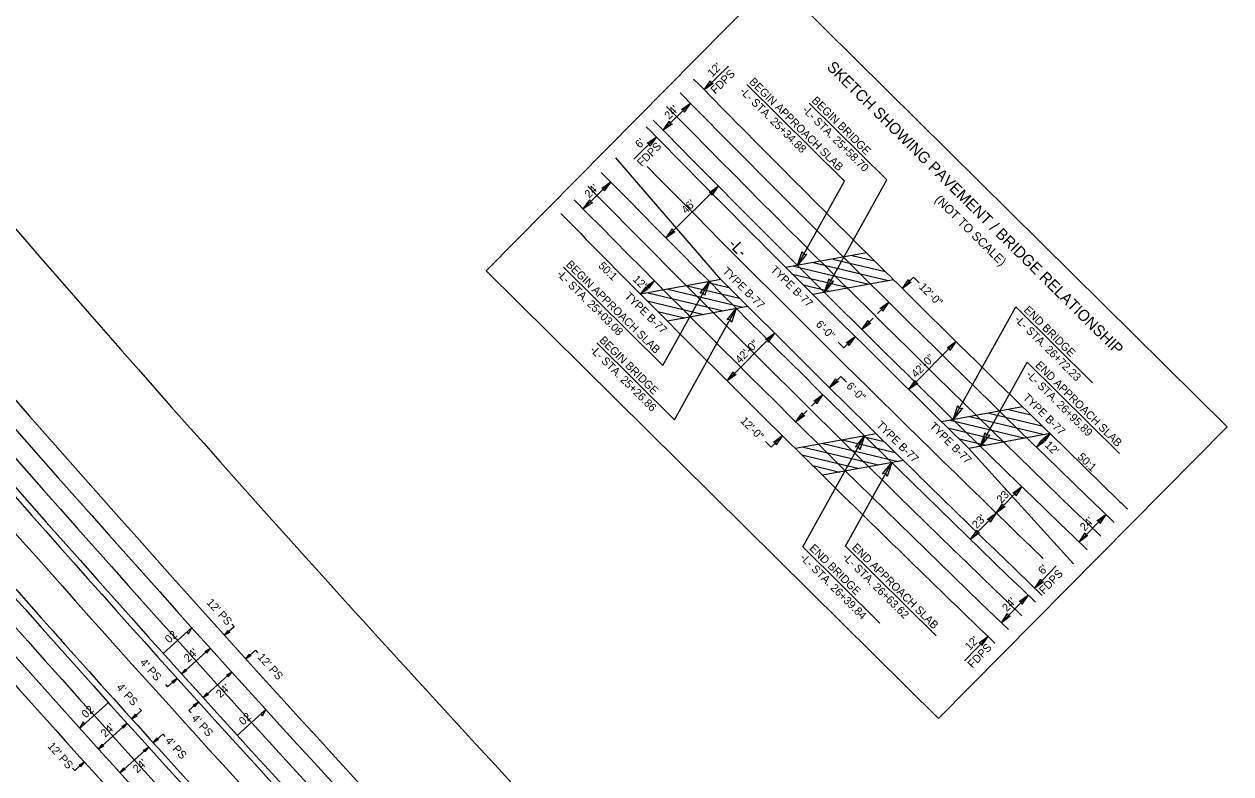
# Model space of a CAD drawing. Extents: x 1602193 to 1605074, y 908180 to 910630.
# Drawn here: x 1602900 to 1603654, y 909541 to 910009 of the extents above; entities that cross this region are included whole.
import ezdxf

# ---------------------------------------------------------------- set-up
doc = ezdxf.new("R2010")
doc.units = 0
for name, color, linetype in [('Prop Approach Slab', 7, 'Continuous'), ('Prop Approach Slab Hatching', 7, 'Continuous'), ('Prop Cable Guiderail Double Face', 7, 'Continuous'), ('Prop Dimension', 7, 'Continuous'), ('Prop Dimension Text', 7, 'Continuous'), ('Prop DSN Text', 7, 'Continuous'), ('Prop EOT', 7, 'Continuous'), ('Prop Fence Woven Wire', 7, 'Continuous'), ('Prop Horizontal Alignment', 7, 'Continuous'), ('Prop Horizontal Alignment Station Label', 7, 'Continuous'), ('Prop Lane Lines', 7, 'Continuous'), ('Prop Paved Shoulder', 7, 'Continuous'), ('Prop Roadway Bridge', 7, 'Continuous'), ('Prop Structure Anchor Unit CELL', 7, 'Continuous'), ('Prop Superelevation  Arrow CELL', 7, 'Continuous'), ('Prop Superelevation Label', 7, 'Continuous'), ('Prop Terminator CELL', 7, 'Continuous')]:
    doc.layers.add(name, color=color, linetype=linetype)

msp = doc.modelspace()

# ---------------------------------------------------------------- linework, layer by layer
at = {"layer": 'Prop Approach Slab'}
for p, q in [((1603426.15, 909865.89), (1603375.89, 909856.69)), ((1603335.26, 909849.24), (1603285.14, 909840.06)), ((1603540.84, 909753.06), (1603490.19, 909743.78)), ((1603449.24, 909736.28), (1603398.73, 909727.02))]:
    msp.add_line(p, q, dxfattribs=at)
for radius, start, end in [(14299.86, 225.146584, 225.241734), (14341.86, 225.030204, 225.124941), (14375.86, 224.936597, 225.031002), (14417.86, 224.821732, 224.915732), (14299.86, 225.695412, 225.791225), (14341.86, 225.576639, 225.672031), (14375.86, 225.481114, 225.576185), (14417.86, 225.3639, 225.458558)]:
    msp.add_arc((1613511.77, 920003.26), radius, start, end, dxfattribs=at)
at = {"layer": 'Prop Approach Slab Hatching'}
for p, q in [((1603392.97, 909859.82), (1603439.87, 909848.59)), ((1603405.14, 909862.04), (1603437.92, 909854.19)), ((1603417.3, 909864.27), (1603431.1, 909860.97)), ((1603379.93, 909852.66), (1603415.54, 909844.13)), ((1603380.81, 909857.59), (1603427.71, 909846.36)), ((1603302.09, 909843.17), (1603348.99, 909831.94)), ((1603314.25, 909845.4), (1603346.92, 909837.57)), ((1603326.42, 909847.62), (1603340.17, 909844.33)), ((1603386.71, 909845.89), (1603403.38, 909841.9)), ((1603289.2, 909835.97), (1603324.66, 909827.48)), ((1603289.93, 909840.94), (1603336.82, 909829.71)), ((1603295.92, 909829.22), (1603312.49, 909825.25)), ((1603514.87, 909768.13), (1603528.79, 909764.8)), ((1603478.38, 909761.44), (1603525.28, 909750.21)), ((1603490.54, 909763.67), (1603537.45, 909752.44)), ((1603502.7, 909765.9), (1603535.79, 909757.98)), ((1603477.07, 909756.62), (1603513.12, 909747.98)), ((1603399.05, 909746.91), (1603445.96, 909735.68)), ((1603411.21, 909749.14), (1603444.18, 909741.25)), ((1603423.38, 909751.37), (1603437.25, 909748.05)), ((1603484.02, 909749.81), (1603500.96, 909745.76)), ((1603385.74, 909739.82), (1603421.64, 909731.22)), ((1603386.88, 909744.68), (1603433.8, 909733.45)), ((1603392.63, 909733.03), (1603409.47, 909728.99))]:
    msp.add_line(p, q, dxfattribs=at)
at = {"layer": 'Prop Cable Guiderail Double Face'}
msp.add_arc((1613646.31, 919202), 14354.86, 219.580763, 222.768936, dxfattribs=at)
at = {"layer": 'Prop Dimension Text'}
for p, q in [((1603188.56, 909854.76), (1603368.87, 910036.95)), ((1603368.87, 910036.95), (1603651.42, 909757.33)), ((1603324.84, 909967.7), (1603339.91, 909982.54)), ((1603412.36, 909910.74), (1603351.36, 909971.1)), ((1603299.2, 909942.43), (1603316.3, 909959.28)), ((1603438.86, 909911.46), (1603390.43, 909959.39)), ((1603280.88, 909924.39), (1603294.92, 909938.22)), ((1603383.07, 909858), (1603412.36, 909910.74)), ((1603399.87, 909841.26), (1603438.86, 909911.46)), ((1603249.33, 909893.31), (1603266.43, 909910.15)), ((1603300.98, 909875.2), (1603333.64, 909907.59)), ((1603188.56, 909854.76), (1603471.11, 909575.13)), ((1603299.04, 909795.6), (1603236.97, 909857.03)), ((1603455.65, 909850.7), (1603448.61, 909843.6)), ((1603455.65, 909850.7), (1603459.2, 909847.18)), ((1603293.65, 909848.52), (1603285.14, 909840.06)), ((1603299.04, 909795.6), (1603328.1, 909847.93)), ((1603306.26, 909761.72), (1603344.83, 909831.18)), ((1603440.16, 909835.07), (1603433.13, 909827.97)), ((1603480.35, 909761.81), (1603519.42, 909832.16)), ((1603567.31, 909784.75), (1603519.42, 909832.16)), ((1603430.31, 909825.12), (1603423.27, 909818.02)), ((1603339.12, 909786.03), (1603368.75, 909815.79)), ((1603419.05, 909813.76), (1603412.01, 909806.65)), ((1603306.26, 909761.72), (1603257.75, 909809.73)), ((1603412.01, 909806.65), (1603408.46, 909810.17)), ((1603452.63, 909780.6), (1603482.09, 909810.54)), ((1603497.42, 909745.11), (1603526.62, 909797.68)), ((1603584.32, 909740.57), (1603526.62, 909797.68)), ((1603403.18, 909781.63), (1603410.21, 909788.74)), ((1603410.21, 909788.74), (1603413.76, 909785.23)), ((1603391.93, 909770.26), (1603398.96, 909777.37)), ((1603382.08, 909760.3), (1603389.11, 909767.41)), ((1603471.11, 909575.13), (1603651.42, 909757.33)), ((1603532.47, 909744.46), (1603540.84, 909753.06)), ((1603366.61, 909744.66), (1603363.06, 909748.18)), ((1603366.61, 909744.66), (1603373.64, 909751.77)), ((1603386.49, 909682.32), (1603425.01, 909751.67)), ((1603413.04, 909682.78), (1603442.02, 909734.96)), ((1603507.22, 909703.46), (1603523.24, 909719.96)), ((1603491.19, 909686.97), (1603507.22, 909703.46)), ((1603559.03, 909685.32), (1603575.69, 909702.59)), ((1603434.56, 909634.76), (1603386.49, 909682.32)), ((1603469.68, 909626.73), (1603413.04, 909682.78)), ((1603531.26, 909656.53), (1603544.66, 909670.42)), ((1603510.43, 909634.94), (1603527.1, 909652.21)), ((1603031.16, 909632.47), (1603025.22, 909627.11)), ((1603029.82, 909633.96), (1603031.16, 909632.47)), ((1603502.1, 909626.3), (1603487.42, 909611.08)), ((1602998.5, 909602.99), (1603016.31, 909619.07)), ((1603044.46, 909617.73), (1603038.53, 909612.36)), ((1603044.46, 909617.73), (1603045.81, 909616.25)), ((1603011.92, 909588.12), (1603029.71, 909604.23)), ((1602988.25, 909596.43), (1602989.59, 909594.95)), ((1602995.53, 909600.31), (1602989.59, 909594.95)), ((1602973.26, 909580.21), (1602967.32, 909574.84)), ((1602971.92, 909581.69), (1602973.26, 909580.21)), ((1603008.88, 909585.52), (1603002.95, 909580.15)), ((1603002.95, 909580.15), (1603004.29, 909578.67)), ((1602946.54, 909556.08), (1602964.35, 909572.16)), ((1602986.64, 909565.38), (1602980.71, 909560.01)), ((1602986.64, 909565.38), (1602987.98, 909563.9)), ((1602959.96, 909541.21), (1602977.75, 909557.32)), ((1602930.35, 909544.16), (1602931.69, 909542.68)), ((1602937.63, 909548.04), (1602931.69, 909542.68))]:
    msp.add_line(p, q, dxfattribs=at)
at = {"layer": 'Prop DSN Text'}
for points in [[(1603289.89, 909843.37), (1603285.14, 909840.06), (1603288.48, 909844.79), (1603288.68, 909843.59)], [(1603288.9, 909845.21), (1603293.65, 909848.52), (1603290.31, 909843.79), (1603290.1, 909844.99)], [(1603536.15, 909749.67), (1603540.84, 909753.06), (1603537.58, 909748.28), (1603537.35, 909749.48)], [(1603537.17, 909747.85), (1603532.47, 909744.46), (1603535.73, 909749.25), (1603535.96, 909748.05)], [(1603028.49, 909629.17), (1603025.22, 909627.11), (1603027.59, 909630.16), (1603027.69, 909629.35)], [(1603013.04, 909617.02), (1603016.31, 909619.07), (1603013.93, 909616.03), (1603013.83, 909616.84)], [(1603041.8, 909614.42), (1603038.53, 909612.36), (1603040.9, 909615.41), (1603041, 909614.6)], [(1603001.76, 909605.04), (1602998.5, 909602.99), (1603000.87, 909606.03), (1603000.97, 909605.22)], [(1603026.45, 909602.17), (1603029.71, 909604.23), (1603027.34, 909601.18), (1603027.24, 909601.99)], [(1602992.26, 909598.26), (1602995.53, 909600.31), (1602993.15, 909597.27), (1602993.05, 909598.07)], [(1603015.19, 909590.18), (1603011.92, 909588.12), (1603014.29, 909591.16), (1603014.39, 909590.36)], [(1603005.61, 909583.46), (1603008.88, 909585.52), (1603006.51, 909582.47), (1603006.41, 909583.28)], [(1602961.08, 909570.11), (1602964.35, 909572.16), (1602961.98, 909569.12), (1602961.88, 909569.93)], [(1602970.59, 909576.9), (1602967.32, 909574.84), (1602969.69, 909577.89), (1602969.8, 909577.08)], [(1602949.81, 909558.13), (1602946.54, 909556.08), (1602948.91, 909559.13), (1602949.01, 909558.32)], [(1602974.49, 909555.26), (1602977.75, 909557.32), (1602975.38, 909554.27), (1602975.28, 909555.08)], [(1602983.97, 909562.07), (1602980.71, 909560.01), (1602983.08, 909563.06), (1602983.18, 909562.25)], [(1602934.36, 909545.99), (1602937.63, 909548.04), (1602935.25, 909545), (1602935.15, 909545.81)], [(1602963.23, 909543.27), (1602959.96, 909541.21), (1602962.33, 909544.26), (1602962.43, 909543.45)]]:
    msp.add_lwpolyline(points, close=True, dxfattribs=at)
at = {"layer": 'Prop EOT'}
for centre, radius, start, end in [((1613646.31, 919202), 14311.86, 219.480877, 227.661141), ((1613646.31, 919202), 14335.86, 219.480979, 227.66104), ((1613646.31, 919202), 14381.86, 219.480979, 227.66104), ((1613646.31, 919202), 14405.86, 219.479716, 227.662303), ((1613511.77, 920003.26), 14311.86, 224.534023, 226.061438), ((1613511.77, 920003.26), 14335.86, 224.535302, 226.060159), ((1613511.77, 920003.26), 14381.86, 224.53774, 226.05772), ((1613511.77, 920003.26), 14405.86, 224.539006, 226.056454)]:
    msp.add_arc(centre, radius, start, end, dxfattribs=at)
at = {"layer": 'Prop Fence Woven Wire'}
for centre, radius, start, end in [((1613597.21, 919158.4), 14163.95, 218.093461, 222.076817), ((1613600.64, 919155.95), 14423.95, 219.415042, 223.36309), ((1613597.21, 919158.4), 14163.95, 222.076817, 224.234567)]:
    msp.add_arc(centre, radius, start, end, dxfattribs=at)
at = {"layer": 'Prop Horizontal Alignment'}
msp.add_arc((1613511.77, 920003.26), 14358.86, 224.607069, 225.996232, dxfattribs=at)
at = {"layer": 'Prop Lane Lines'}
for centre, radius, start, end in [((1613646.31, 919202), 14323.86, 219.480979, 227.66104), ((1613646.31, 919202), 14393.86, 219.480979, 227.66104), ((1613511.77, 920003.26), 14323.86, 224.534663, 226.060798), ((1613511.77, 920003.26), 14393.86, 224.538374, 226.057086)]:
    msp.add_arc(centre, radius, start, end, dxfattribs=at)
at = {"layer": 'Prop Paved Shoulder'}
for p, q in [((1603335.26, 909849.24), (1603269.59, 909925.26)), ((1603540.84, 909753.06), (1603583.87, 909711.07)), ((1603490.19, 909743.78), (1603555.43, 909671.71))]:
    msp.add_line(p, q, dxfattribs=at)
for centre, radius, start, end in [((1613646.31, 919202), 14299.86, 219.480979, 223.794464), ((1613646.31, 919202), 14339.86, 219.480979, 222.863015), ((1613646.31, 919202), 14377.86, 219.48119, 222.373049), ((1613646.31, 919202), 14417.86, 219.480979, 222.382421), ((1613511.77, 920003.26), 14299.86, 224.533383, 225.146584), ((1613511.77, 920003.26), 14341.86, 224.535621, 225.030203), ((1613511.77, 920003.26), 14417.86, 224.539638, 224.821732), ((1613511.77, 920003.26), 14375.86, 225.576185, 226.058037), ((1613511.77, 920003.26), 14417.86, 225.458558, 226.055822), ((1613511.62, 920003.1), 14299.86, 226.032131, 226.061438)]:
    msp.add_arc(centre, radius, start, end, dxfattribs=at)
at = {"layer": 'Prop Roadway Bridge'}
for p, q in [((1603443, 909849.16), (1603392.69, 909839.94)), ((1603352.01, 909832.49), (1603301.82, 909823.3)), ((1603523.71, 909769.75), (1603473.12, 909760.48)), ((1603432.22, 909752.99), (1603381.76, 909743.75))]:
    msp.add_line(p, q, dxfattribs=at)
for radius, start, end in [(14299.86, 225.241734, 225.695412), (14341.86, 225.124941, 225.576639), (14375.86, 225.031002, 225.481114), (14417.86, 224.915732, 225.3639)]:
    msp.add_arc((1613511.77, 920003.26), radius, start, end, dxfattribs=at)
at = {"layer": 'Prop Superelevation  Arrow CELL'}
for p, q in [((1603004.76, 909631.9), (1602986.91, 909615.85)), ((1602952.71, 909585.09), (1602934.86, 909569.05)), ((1603050.96, 909580.77), (1603033.2, 909564.64))]:
    msp.add_line(p, q, dxfattribs=at)
for points in [[(1603004.76, 909631.9), (1603002.41, 909627.78), (1603002.18, 909629.58)], [(1603050.96, 909580.77), (1603048.64, 909576.64), (1603048.39, 909578.44)], [(1602934.86, 909569.05), (1602937.21, 909573.17), (1602937.44, 909571.36)]]:
    msp.add_lwpolyline(points, close=True, dxfattribs=at)
at = {"layer": 'Prop Terminator CELL'}
for points in [[(1603330.47, 909971.61), (1603324.84, 909967.7), (1603328.84, 909973.32), (1603329.06, 909971.86)], [(1603310.67, 909955.37), (1603316.3, 909959.28), (1603312.3, 909953.66), (1603312.07, 909955.12)], [(1603304.82, 909946.34), (1603299.2, 909942.43), (1603303.19, 909948.05), (1603303.42, 909946.59)], [(1603289.3, 909934.31), (1603294.92, 909938.22), (1603290.93, 909932.6), (1603290.7, 909934.06)], [(1603260.8, 909906.24), (1603266.43, 909910.15), (1603262.44, 909904.53), (1603262.21, 909905.99)], [(1603328.03, 909903.66), (1603333.64, 909907.59), (1603329.67, 909901.96), (1603329.43, 909903.42)], [(1603254.96, 909897.22), (1603249.33, 909893.31), (1603253.32, 909898.93), (1603253.55, 909897.46)], [(1603306.59, 909879.12), (1603300.98, 909875.2), (1603304.96, 909880.83), (1603305.19, 909879.37)], [(1603388.79, 909865.12), (1603383.07, 909858), (1603386.06, 909866.69), (1603386.9, 909864.91)], [(1603388.79, 909865.12), (1603383.07, 909858), (1603386.06, 909866.69), (1603386.9, 909864.91)], [(1603322.37, 909840.82), (1603328.1, 909847.93), (1603325.1, 909839.24), (1603324.26, 909841.03)], [(1603405.59, 909848.37), (1603399.87, 909841.26), (1603402.86, 909849.95), (1603403.7, 909848.16)], [(1603405.59, 909848.37), (1603399.87, 909841.26), (1603402.86, 909849.95), (1603403.7, 909848.16)], [(1603454.18, 909847.57), (1603448.61, 909843.6), (1603452.53, 909849.26), (1603452.78, 909847.81)], [(1603339.11, 909824.06), (1603344.83, 909831.18), (1603341.84, 909822.49), (1603341, 909824.27)], [(1603339.11, 909824.06), (1603344.83, 909831.18), (1603341.84, 909822.49), (1603341, 909824.27)], [(1603434.59, 909831.09), (1603440.16, 909835.07), (1603436.24, 909829.4), (1603435.99, 909830.86)], [(1603428.85, 909822), (1603423.27, 909818.02), (1603427.2, 909823.69), (1603427.44, 909822.23)], [(1603363.17, 909811.83), (1603368.75, 909815.79), (1603364.82, 909810.13), (1603364.57, 909811.59)], [(1603413.48, 909809.78), (1603419.05, 909813.76), (1603415.13, 909808.09), (1603414.88, 909809.55)], [(1603476.53, 909806.54), (1603482.09, 909810.54), (1603478.19, 909804.86), (1603477.94, 909806.32)], [(1603344.71, 909789.99), (1603339.12, 909786.03), (1603343.06, 909791.68), (1603343.3, 909790.22)], [(1603408.75, 909785.61), (1603403.18, 909781.63), (1603407.1, 909787.3), (1603407.34, 909785.84)], [(1603458.2, 909784.6), (1603452.63, 909780.6), (1603456.54, 909786.28), (1603456.79, 909784.83)], [(1603393.38, 909773.38), (1603398.96, 909777.37), (1603395.04, 909771.7), (1603394.79, 909773.15)], [(1603486.07, 909768.92), (1603480.35, 909761.81), (1603483.34, 909770.49), (1603484.18, 909768.71)], [(1603486.07, 909768.92), (1603480.35, 909761.81), (1603483.34, 909770.49), (1603484.18, 909768.71)], [(1603387.65, 909764.28), (1603382.08, 909760.3), (1603386, 909765.97), (1603386.25, 909764.51)], [(1603503.15, 909752.22), (1603497.42, 909745.11), (1603500.42, 909753.8), (1603501.26, 909752.01)], [(1603503.15, 909752.22), (1603497.42, 909745.11), (1603500.42, 909753.8), (1603501.26, 909752.01)], [(1603368.07, 909747.79), (1603373.64, 909751.77), (1603369.72, 909746.1), (1603369.48, 909747.56)], [(1603419.28, 909744.55), (1603425.01, 909751.67), (1603422.01, 909742.98), (1603421.17, 909744.76)], [(1603419.28, 909744.55), (1603425.01, 909751.67), (1603422.01, 909742.98), (1603421.17, 909744.76)], [(1603436.3, 909727.84), (1603442.02, 909734.96), (1603439.03, 909726.27), (1603438.19, 909728.05)], [(1603517.71, 909715.93), (1603523.24, 909719.96), (1603519.38, 909714.26), (1603519.12, 909715.71)], [(1603512.76, 909707.5), (1603507.22, 909703.46), (1603511.09, 909709.17), (1603511.35, 909707.71)], [(1603501.68, 909699.43), (1603507.22, 909703.46), (1603503.35, 909697.76), (1603503.09, 909699.21)], [(1603570.17, 909698.54), (1603575.69, 909702.59), (1603571.85, 909696.87), (1603571.58, 909698.33)], [(1603496.73, 909691), (1603491.19, 909686.97), (1603495.06, 909692.67), (1603495.32, 909691.22)], [(1603564.56, 909689.37), (1603559.03, 909685.32), (1603562.88, 909691.04), (1603563.15, 909689.58)], [(1603536.79, 909660.58), (1603531.26, 909656.53), (1603535.11, 909662.25), (1603535.38, 909660.79)], [(1603521.57, 909648.16), (1603527.1, 909652.21), (1603523.25, 909646.49), (1603522.98, 909647.95)], [(1603515.96, 909638.99), (1603510.43, 909634.94), (1603514.28, 909640.66), (1603514.55, 909639.2)], [(1603498.25, 909620.64), (1603502.1, 909626.3), (1603496.53, 909622.25), (1603497.99, 909622.04)]]:
    msp.add_lwpolyline(points, close=True, dxfattribs=at)

# ---------------------------------------------------------------- texts
at = {"layer": 'Prop Dimension'}
for s, height, p in [('SKETCH SHOWING PAVEMENT / BRIDGE RELATIONSHIP', 7, (1603400.9, 909981.34)), ('(NOT TO SCALE)', 5.5, (1603468.44, 909898.67))]:
    msp.add_text(s, height=height, rotation=315.29764, dxfattribs=at).set_placement(p)
at = {"layer": 'Prop Dimension Text'}
for s, rotation, p in [("12'", 44.57114, (1603329.83, 909975.41)), ('FDPS', 44.57114, (1603331.78, 909964.71)), ('BEGIN APPROACH SLAB', 315.29764, (1603352.53, 909972.29)), ('-L- STA. 25+34.88', 315.29764, (1603346.67, 909966.37)), ('BEGIN BRIDGE', 315.29764, (1603391.6, 909960.57)), ("24'", 44.57114, (1603302.88, 909948.87)), ('-L- STA. 25+58.70', 315.29764, (1603385.74, 909954.65)), ("6'", 44.57114, (1603284.63, 909930.89)), ('FDPS', 44.57114, (1603285.79, 909919.4)), ("24'", 44.57114, (1603253.01, 909899.74)), ("46'", 44.76694, (1603313.5, 909889.96)), ('BEGIN APPROACH SLAB', 315.29764, (1603238.14, 909858.21)), ('50:1', 315.70105, (1603258.32, 909857.34)), ('-L- STA. 25+03.08', 315.29764, (1603232.28, 909852.29)), ("12'", 315.29764, (1603279.82, 909848.94)), ('12\'-0"', 315.29764, (1603458.63, 909844.23)), ('END BRIDGE', 315.29764, (1603524.14, 909829.82)), ('6\'-0"', 315.29764, (1603394.16, 909820.81)), ('-L- STA. 26+72.23', 315.29764, (1603518.28, 909823.9)), ('BEGIN BRIDGE', 315.29764, (1603258.93, 909810.92)), ('-L- STA. 25+26.86', 315.29764, (1603253.06, 909804.99)), ('42\'-0"', 45.12527, (1603347.19, 909796.49)), ('42\'-0"', 45.46191, (1603457.18, 909787.6)), ('END APPROACH SLAB', 315.29764, (1603531.34, 909795.35)), ('-L- STA. 26+95.89', 315.29764, (1603525.48, 909789.42)), ('6\'-0"', 315.29764, (1603413.19, 909782.28)), ('12\'-0"', 315.29764, (1603347.02, 909760.53)), ("12'", 315.29764, (1603537.26, 909745.4)), ('50:1', 315.70105, (1603557.64, 909738.06)), ("23'", 45.83306, (1603510.46, 909709.19)), ("23'", 45.83306, (1603495.12, 909693.38)), ("24'", 46.03213, (1603562.55, 909691.85)), ('END APPROACH SLAB', 315.29764, (1603416.7, 909681.5)), ('END BRIDGE', 315.29764, (1603390.15, 909681.04)), ('-L- STA. 26+63.62', 315.29764, (1603410.84, 909675.58)), ('-L- STA. 26+39.84', 315.29764, (1603384.29, 909675.12)), ("6'", 46.03213, (1603536.39, 909664.72)), ('FDPS', 46.03213, (1603536.99, 909652.39)), ("12' PS", 312.07466, (1603013.65, 909647.33)), ("24'", 46.03213, (1603513.95, 909641.46)), ("12'", 46.03213, (1603490.66, 909617.32)), ("24'", 42.07466, (1603002.55, 909609.98)), ('FDPS', 46.03213, (1603492.46, 909606.22)), ("4' PS", 312.07466, (1602971.98, 909609.87)), ("12' PS", 312.15427, (1603045.49, 909613.19)), ("4' PS", 312.07466, (1602957.37, 909594.36)), ("24'", 42.15472, (1603022.64, 909587.74)), ("24'", 42.07466, (1602950.59, 909563.07)), ("4' PS", 312.15427, (1603004.25, 909575.03)), ("12' PS", 312.07466, (1602914.31, 909557.66)), ("4' PS", 312.15427, (1602987.82, 909561.02)), ("24'", 42.15472, (1602970.68, 909540.83))]:
    msp.add_text(s, height=5, rotation=rotation, dxfattribs=at).set_placement(p)
at = {"layer": 'Prop Horizontal Alignment Station Label'}
msp.add_text('-L-', height=7, rotation=315.10236, dxfattribs=at).set_placement((1603339.45, 909870.81))
at = {"layer": 'Prop Structure Anchor Unit CELL'}
for p in [(1603365.94, 909854.93), (1603335.84, 909853.93), (1603274.81, 909838.39), (1603523.6, 909775.11), (1603432.04, 909757.89), (1603465.08, 909757.15)]:
    msp.add_text('TYPE B-77', height=5, rotation=315.40639, dxfattribs=at).set_placement(p)
at = {"layer": 'Prop Superelevation Label'}
for rotation, p in [(41.96551, (1602990.64, 909621.89)), (41.96551, (1602938.59, 909575.08)), (42.24141, (1603036.89, 909570.69))]:
    msp.add_text('02', height=5, rotation=rotation, dxfattribs=at).set_placement(p)

doc.saveas('drawing.dxf')
